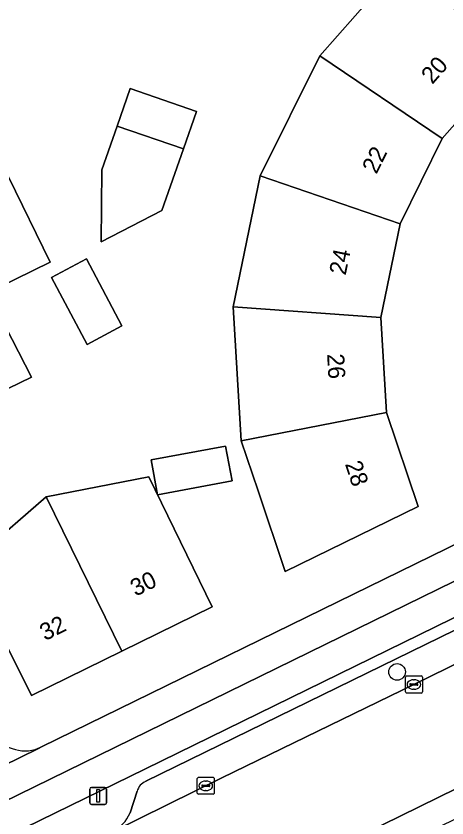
# Model space of a CAD drawing. Extents: x 160455 to 162082, y 388339 to 389736.
# Drawn here: x 160753.79 to 160779.09, y 388835.85 to 388882.97 of the extents above; entities that cross this region are included whole.
import ezdxf

# ---------------------------------------------------------------- set-up
doc = ezdxf.new("R2010")
doc.units = 0
for name, color, linetype in [('IMGEO_Berm_groen', 7, 'Continuous'), ('IMGEO_Boom', 7, 'Continuous'), ('IMGEO_Erf', 7, 'Continuous'), ('IMGEO_Fietspad_gesloten', 7, 'Continuous'), ('IMGEO_Kolk', 7, 'Continuous'), ('IMGEO_Lichtmast', 7, 'Continuous'), ('IMGEO_Pand', 7, 'Continuous'), ('IMGEO_Pand_nummerreeks', 7, 'Continuous'), ('IMGEO_Parkeervlak_open', 7, 'Continuous'), ('IMGEO_Rijbaan_lokaal_gesloten', 7, 'Continuous'), ('IMGEO_Verkeerseiland_open', 7, 'Continuous'), ('IMGEO_Voetpad_open', 7, 'Continuous')]:
    doc.layers.add(name, color=color, linetype=linetype)

msp = doc.modelspace()

# ---------------------------------------------------------------- linework, layer by layer
at = {"layer": 'IMGEO_Berm_groen'}
msp.add_lwpolyline([(160784.31, 388838.109), (160783.606, 388839.551), (160780.719, 388838.113), (160774.22, 388834.916), (160774.906, 388833.514)], close=True, dxfattribs=at)
at = {"layer": 'IMGEO_Boom'}
msp.add_circle((160776.158, 388844.434), 0.489, dxfattribs=at)
at = {"layer": 'IMGEO_Erf'}
for points in [[(160702.295, 388943.534), (160746.543, 388853.042), (160750.115, 388854.798), (160751.768, 388851.437), (160755.566, 388854.723), (160761.578, 388855.902), (160765.312, 388848.254), (160760.001, 388845.647), (160754.69, 388843.04), (160753.115, 388846.244), (160750.513, 388844.965), (160752.505, 388840.773)], [(160787.369, 388883.189), (160782.515, 388879.97), (160778.818, 388875.773), (160776.334, 388870.756), (160775.212, 388865.262), (160775.533, 388859.681), (160777.391, 388854.151), (160769.582, 388850.325), (160767.997, 388855.068), (160767.014, 388858.009), (160766.541, 388865.875), (160768.123, 388873.58), (160771.624, 388880.626), (160776.809, 388886.524)], [(160753.342, 388873.528), (160755.794, 388868.515), (160746.63, 388864.032)], [(160755.282, 388840.029), (160778.156, 388851.243), (160781.005, 388852.621)]]:
    msp.add_lwpolyline(points, dxfattribs=at)
for points in [[(160760.493, 388878.711), (160764.379, 388877.354), (160763.616, 388875.167), (160762.354, 388871.551), (160758.785, 388869.702), (160758.826, 388873.934), (160759.721, 388876.499)], [(160757.918, 388868.699), (160760.001, 388864.764), (160757.96, 388863.676), (160755.877, 388867.612)], [(160750.812, 388864.45), (160752.786, 388865.452), (160754.688, 388861.756), (160752.624, 388860.747), (160750.319, 388859.62), (160748.507, 388863.323)], [(160766.089, 388857.706), (160766.472, 388855.659), (160762.1, 388854.842), (160761.717, 388856.888)]]:
    msp.add_lwpolyline(points, close=True, dxfattribs=at)
msp.add_arc((160754.308, 388841.947), 2.151, 213.074, 296.9297, dxfattribs=at)
at = {"layer": 'IMGEO_Fietspad_gesloten'}
msp.add_lwpolyline([(160935.958, 388926.245), (160935.472, 388926.041), (160929.623, 388923.115), (160929.542, 388923.081), (160924.149, 388920.448), (160820.314, 388869.678), (160812.524, 388865.895), (160804.151, 388861.828), (160752.018, 388836.29), (160739.38, 388830.051), (160696.889, 388809.242), (160688.114, 388804.953), (160688.97, 388803.215), (160707.492, 388812.318), (160716.69, 388816.833), (160716.639, 388816.936), (160723.758, 388820.418), (160723.804, 388820.325), (160740.999, 388828.766), (160761.388, 388838.743), (160804.958, 388860.084), (160820.353, 388867.581)], dxfattribs=at)
at = {"layer": 'IMGEO_Kolk'}
for p, q in [((160776.646, 388843.269), (160776.646, 388844.121)), ((160776.721, 388844.195), (160777.573, 388844.195)), ((160777.134, 388843.975), (160777.159, 388843.975)), ((160777.647, 388844.121), (160777.647, 388843.269)), ((160776.905, 388843.689), (160776.905, 388843.701)), ((160777.343, 388843.652), (160776.945, 388843.652)), ((160776.948, 388843.738), (160777.346, 388843.738)), ((160777.157, 388843.415), (160777.132, 388843.415)), ((160777.389, 388843.701), (160777.389, 388843.689)), ((160777.573, 388843.195), (160776.721, 388843.195)), ((160764.505, 388838.243), (160765.357, 388838.243)), ((160764.43, 388837.317), (160764.43, 388838.169)), ((160764.689, 388837.737), (160764.689, 388837.749)), ((160764.732, 388837.786), (160765.13, 388837.786)), ((160764.918, 388838.023), (160764.943, 388838.023)), ((160765.173, 388837.749), (160765.173, 388837.737)), ((160765.431, 388838.169), (160765.431, 388837.317)), ((160765.357, 388837.243), (160764.505, 388837.243)), ((160765.127, 388837.7), (160764.729, 388837.7)), ((160764.941, 388837.463), (160764.916, 388837.463))]:
    msp.add_line(p, q, dxfattribs=at)
for points in [[(160776.646, 388843.269), (160776.646, 388844.121)], [(160776.721, 388844.195), (160777.573, 388844.195)], [(160777.647, 388844.121), (160777.647, 388843.269)], [(160777.573, 388843.195), (160776.721, 388843.195)], [(160764.505, 388838.243), (160765.357, 388838.243)], [(160764.43, 388837.317), (160764.43, 388838.169)], [(160765.431, 388838.169), (160765.431, 388837.317)], [(160765.357, 388837.243), (160764.505, 388837.243)]]:
    msp.add_lwpolyline(points, dxfattribs=at)
for centre, radius, start, end in [((160776.723, 388844.119), 0.0765, 91.552, 178.448), ((160776.723, 388844.119), 0.0765, 91.552, 178.448), ((160777.571, 388844.119), 0.0765, 1.552, 88.448), ((160777.571, 388844.119), 0.0765, 1.552, 88.448), ((160776.945, 388843.698), 0.0403, 85.8775, 175.7526), ((160776.942, 388843.688), 0.0366, 178.938, 274.7102), ((160777.346, 388843.695), 0.043, 264.8664, 352.4533), ((160777.35, 388843.7), 0.0386, 1.7309, 96.639), ((160776.723, 388843.271), 0.0765, 181.552, 268.448), ((160776.723, 388843.271), 0.0765, 181.552, 268.448), ((160777.571, 388843.271), 0.0765, 271.552, 358.448), ((160777.571, 388843.271), 0.0765, 271.552, 358.448), ((160764.507, 388838.167), 0.0765, 91.552, 178.448), ((160764.507, 388838.167), 0.0765, 91.552, 178.448), ((160765.355, 388838.167), 0.0765, 1.552, 88.448), ((160765.355, 388838.167), 0.0765, 1.552, 88.448), ((160764.729, 388837.746), 0.0403, 85.8775, 175.7526), ((160764.726, 388837.736), 0.0366, 178.938, 274.7102), ((160765.13, 388837.743), 0.043, 264.8664, 352.4533), ((160765.134, 388837.748), 0.0386, 1.7309, 96.639), ((160764.507, 388837.319), 0.0765, 181.552, 268.448), ((160764.507, 388837.319), 0.0765, 181.552, 268.448), ((160765.355, 388837.319), 0.0765, 271.552, 358.448), ((160765.355, 388837.319), 0.0765, 271.552, 358.448)]:
    msp.add_arc(centre, radius, start, end, dxfattribs=at)
for centre, major_axis, ratio, start_param, end_param in [((160777.133, 388843.695), (-0.387, 0.002), 0.722429, 4.712389, 7.853982), ((160777.158, 388843.695), (-0.39, 0.002), 0.717154, 1.570796, 4.712389), ((160764.917, 388837.743), (-0.387, 0.002), 0.722429, 4.712389, 7.853982), ((160764.942, 388837.743), (-0.39, 0.002), 0.717154, 1.570796, 4.712389)]:
    msp.add_ellipse(centre, major_axis=major_axis, ratio=ratio, start_param=start_param, end_param=end_param, dxfattribs=at)
at = {"layer": 'IMGEO_Lichtmast'}
for p, q in [((160758.115, 388836.749), (160758.115, 388837.549)), ((160758.115, 388837.549), (160758.115, 388836.749)), ((160758.215, 388837.649), (160759.005, 388837.649)), ((160759.005, 388837.649), (160758.215, 388837.649)), ((160759.105, 388837.549), (160759.105, 388836.749)), ((160759.105, 388836.749), (160759.105, 388837.549)), ((160759.005, 388836.649), (160758.215, 388836.649)), ((160758.215, 388836.649), (160759.005, 388836.649))]:
    msp.add_line(p, q, dxfattribs=at)
msp.add_lwpolyline([(160758.535, 388837.524), (160758.685, 388837.524), (160758.685, 388836.774), (160758.535, 388836.774), (160758.535, 388837.524)], dxfattribs=at)
for centre, start, end in [((160758.215, 388837.549), 90, 180), ((160758.215, 388837.549), 90, 180), ((160759.005, 388837.549), 0, 90), ((160759.005, 388837.549), 360, 90), ((160758.215, 388836.749), 180, 270), ((160758.215, 388836.749), 180, 270), ((160759.005, 388836.749), 270, 0), ((160759.005, 388836.749), 270, 0)]:
    msp.add_arc(centre, 0.1, start, end, dxfattribs=at)
at = {"layer": 'IMGEO_Pand'}
for points in [[(160771.624, 388880.626), (160778.818, 388875.773), (160782.515, 388879.97), (160776.809, 388886.524)], [(160743.031, 388878.682), (160744.402, 388875.881), (160739.785, 388873.622), (160741.614, 388869.885), (160742.18, 388870.162), (160742.864, 388868.756), (160742.295, 388868.485), (160742.434, 388868.193), (160744.178, 388869.046), (160746.63, 388864.032), (160755.794, 388868.515), (160753.342, 388873.528), (160751.802, 388876.678), (160752.565, 388877.051), (160750.081, 388882.13)], [(160771.624, 388880.626), (160768.123, 388873.58), (160776.334, 388870.756), (160778.818, 388875.773)], [(160759.721, 388876.499), (160763.616, 388875.167), (160764.379, 388877.354), (160760.493, 388878.711)], [(160763.616, 388875.167), (160759.721, 388876.499), (160758.826, 388873.934), (160758.785, 388869.702), (160762.354, 388871.551)], [(160766.541, 388865.875), (160775.212, 388865.262), (160776.334, 388870.756), (160768.123, 388873.58)], [(160755.877, 388867.612), (160757.96, 388863.676), (160760.001, 388864.764), (160757.918, 388868.699)], [(160767.014, 388858.009), (160775.533, 388859.681), (160775.212, 388865.262), (160766.541, 388865.875)], [(160752.786, 388865.452), (160750.812, 388864.45), (160752.624, 388860.747), (160754.688, 388861.756)], [(160767.014, 388858.009), (160767.997, 388855.068), (160769.582, 388850.325), (160777.391, 388854.151), (160775.533, 388859.681)], [(160766.089, 388857.706), (160761.717, 388856.888), (160762.1, 388854.842), (160766.472, 388855.659)], [(160755.566, 388854.723), (160760.001, 388845.647), (160765.312, 388848.254), (160761.578, 388855.902)], [(160755.566, 388854.723), (160751.768, 388851.437), (160750.115, 388854.798), (160746.543, 388853.042), (160750.513, 388844.965), (160753.115, 388846.244), (160754.69, 388843.04), (160760.001, 388845.647)]]:
    msp.add_lwpolyline(points, close=True, dxfattribs=at)
at = {"layer": 'IMGEO_Parkeervlak_open'}
for points in [[(160805.502, 388859.58), (160761.409, 388838.006)], [(160759.446, 388835.039), (160765.876, 388838.21), (160777.148, 388843.694), (160792.12, 388851.034), (160804.857, 388857.276), (160809.001, 388859.296)], [(160760.894, 388837.42), (160760.48, 388836.156)]]:
    msp.add_lwpolyline(points, dxfattribs=at)
for centre, radius, start, end in [((160761.755, 388837.182), 0.893, 112.8026, 164.5769), ((160758.419, 388837.027), 2.238, 297.3266, 337.0929)]:
    msp.add_arc(centre, radius, start, end, dxfattribs=at)
at = {"layer": 'IMGEO_Rijbaan_lokaal_gesloten'}
for points in [[(160809.001, 388859.296), (160804.857, 388857.276), (160792.12, 388851.034), (160777.148, 388843.694), (160765.876, 388838.21), (160759.446, 388835.039)], [(160774.22, 388834.916), (160780.719, 388838.113), (160783.606, 388839.551), (160790.86, 388843.095), (160796.469, 388845.835), (160799.325, 388847.252), (160806.662, 388850.833), (160809.515, 388852.195)]]:
    msp.add_lwpolyline(points, dxfattribs=at)
at = {"layer": 'IMGEO_Verkeerseiland_open'}
for points in [[(160902.415, 388905.053), (160903.765, 388905.697), (160903.541, 388906.153), (160910.727, 388909.682), (160909.887, 388911.468), (160820.353, 388867.581), (160804.958, 388860.084), (160761.388, 388838.743), (160740.999, 388828.766), (160723.804, 388820.325), (160724.107, 388819.706), (160738.585, 388826.804), (160740.267, 388827.638)], [(160761.409, 388838.006), (160805.502, 388859.58)], [(160760.48, 388836.156), (160760.894, 388837.42)]]:
    msp.add_lwpolyline(points, dxfattribs=at)
for centre, radius, start, end in [((160761.755, 388837.182), 0.893, 112.8026, 164.5769), ((160758.419, 388837.027), 2.238, 297.3266, 337.0929)]:
    msp.add_arc(centre, radius, start, end, dxfattribs=at)
at = {"layer": 'IMGEO_Voetpad_open'}
for points in [[(160752.018, 388836.29), (160804.151, 388861.828), (160812.524, 388865.895), (160811.654, 388867.688), (160809.025, 388866.383), (160808.765, 388866.339), (160802.655, 388863.332), (160800.8, 388862.421), (160794.684, 388859.431), (160792.99, 388858.505), (160782.642, 388853.456), (160781.005, 388852.621), (160778.156, 388851.243), (160755.282, 388840.029), (160755.104, 388839.929), (160749.832, 388837.359)], [(160749.315, 388838.459), (160749.558, 388837.942), (160749.832, 388837.359), (160755.104, 388839.929), (160755.282, 388840.029)]]:
    msp.add_lwpolyline(points, dxfattribs=at)
msp.add_arc((160754.308, 388841.947), 2.151, 213.074, 296.9297, dxfattribs=at)

# ---------------------------------------------------------------- texts
at = {"layer": 'IMGEO_Pand_nummerreeks'}
for s, rotation, p in [('20', 48.6242, (160778.231, 388878.919)), ('22', 63.6592, (160774.95, 388873.639)), ('24', 78.4576, (160773.139, 388867.703)), ('26', 273.2918, (160772.05, 388863.108)), ('28', 288.5716, (160773.09, 388856.651)), ('30', 26.1449, (160760.807, 388848.85)), ('32', 26.1449, (160755.491, 388846.241))]:
    msp.add_text(s, height=1, rotation=rotation, dxfattribs=at).set_placement(p)

doc.saveas('drawing.dxf')
